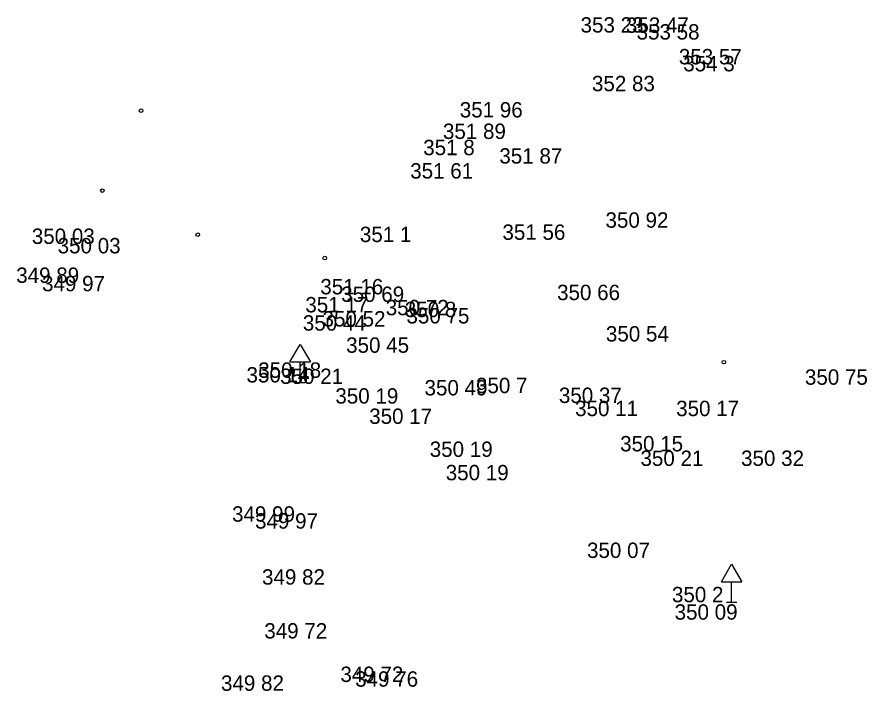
# Model space of a CAD drawing. Extents: x -688316 to -688024, y -973785 to -973591.
# Drawn here: x -688234.74 to -688193.31, y -973766.48 to -973733.6 of the extents above; entities that cross this region are included whole.
import ezdxf

# ---------------------------------------------------------------- set-up
doc = ezdxf.new("R2010")
doc.units = 0
for name, color, linetype in [('Vrstva 3', 7, 'Continuous'), ('Vrstva 34', 7, 'Continuous'), ('Vrstva 58', 7, 'Continuous')]:
    doc.layers.add(name, color=color, linetype=linetype)

# ---------------------------------------------------------------- blocks, each defined once
blk = doc.blocks.new('DZ')
at = {"layer": 'Vrstva 34'}
for p, q in [((-5, 10), (0, 18.5)), ((0, 18.5), (5, 10)), ((-5, 10), (5, 10)), ((0, 0), (0, 10)), ((-2.49, 0), (2.49, 0))]:
    blk.add_line(p, q, dxfattribs=at)
blk = doc.blocks.new('B_NESP')
at = {"layer": 'Vrstva 58'}
blk.add_circle((0, 0), 0.875, dxfattribs=at)

msp = doc.modelspace()

# ---------------------------------------------------------------- block references
at = {"layer": 'Vrstva 34', "xscale": 0.1, "yscale": 0.10000000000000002}
for p in [(-688220.94, -973751.43), (-688220.94, -973751.43), (-688199.91, -973762.15), (-688199.91, -973762.15)]:
    msp.add_blockref('DZ', p, dxfattribs=at)
at = {"layer": 'Vrstva 58', "xscale": 0.1, "yscale": 0.10000000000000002}
for p in [(-688228.69, -973738.17), (-688228.69, -973738.17), (-688230.58, -973742.07), (-688230.58, -973742.07), (-688225.93, -973744.22), (-688225.93, -973744.22), (-688219.74, -973745.36), (-688219.74, -973745.36), (-688200.29, -973750.44), (-688200.29, -973750.44)]:
    msp.add_blockref('B_NESP', p, dxfattribs=at)

# ---------------------------------------------------------------- texts
at = {"layer": 'Vrstva 3'}
for s, p in [('353 23 ', (-688207.271, -973734.36)), ('353 23 ', (-688207.271, -973734.36)), ('353 23 ', (-688207.271, -973734.36)), ('353 23 ', (-688207.271, -973734.36)), ('353 23 ', (-688207.271, -973734.36)), ('353 23 ', (-688207.271, -973734.36)), ('353 23 ', (-688207.271, -973734.36)), ('353 47 ', (-688205.061, -973734.37)), ('353 47 ', (-688205.061, -973734.37)), ('353 47 ', (-688205.061, -973734.37)), ('353 47 ', (-688205.061, -973734.37)), ('353 47 ', (-688205.061, -973734.37)), ('353 47 ', (-688205.061, -973734.37)), ('353 47 ', (-688205.061, -973734.37)), ('353 58 ', (-688204.541, -973734.7)), ('353 58 ', (-688204.541, -973734.7)), ('353 58 ', (-688204.541, -973734.7)), ('353 58 ', (-688204.541, -973734.7)), ('353 58 ', (-688204.541, -973734.7)), ('353 58 ', (-688204.541, -973734.7)), ('353 58 ', (-688204.541, -973734.7)), ('353 57 ', (-688202.481, -973735.91)), ('353 57 ', (-688202.481, -973735.91)), ('353 57 ', (-688202.481, -973735.91)), ('353 57 ', (-688202.481, -973735.91)), ('353 57 ', (-688202.481, -973735.91)), ('353 57 ', (-688202.481, -973735.91)), ('353 57 ', (-688202.481, -973735.91)), ('354 3  ', (-688202.268, -973736.25)), ('354 3  ', (-688202.268, -973736.25)), ('354 3  ', (-688202.268, -973736.25)), ('354 3  ', (-688202.268, -973736.25)), ('354 3  ', (-688202.268, -973736.25)), ('354 3  ', (-688202.268, -973736.25)), ('354 3  ', (-688202.268, -973736.25)), ('352 83 ', (-688206.717, -973737.22)), ('352 83 ', (-688206.717, -973737.22)), ('352 83 ', (-688206.717, -973737.22)), ('352 83 ', (-688206.717, -973737.22)), ('352 83 ', (-688206.717, -973737.22)), ('352 83 ', (-688206.717, -973737.22)), ('352 83 ', (-688206.717, -973737.22)), ('351 96 ', (-688213.159, -973738.5)), ('351 96 ', (-688213.159, -973738.5)), ('351 96 ', (-688213.159, -973738.5)), ('351 96 ', (-688213.159, -973738.5)), ('351 96 ', (-688213.159, -973738.5)), ('351 96 ', (-688213.159, -973738.5)), ('351 96 ', (-688213.159, -973738.5)), ('351 89 ', (-688213.979, -973739.55)), ('351 89 ', (-688213.979, -973739.55)), ('351 89 ', (-688213.979, -973739.55)), ('351 89 ', (-688213.979, -973739.55)), ('351 89 ', (-688213.979, -973739.55)), ('351 89 ', (-688213.979, -973739.55)), ('351 89 ', (-688213.979, -973739.55)), ('351 8  ', (-688214.941, -973740.34)), ('351 8  ', (-688214.941, -973740.34)), ('351 8  ', (-688214.941, -973740.34)), ('351 8  ', (-688214.941, -973740.34)), ('351 8  ', (-688214.941, -973740.34)), ('351 8  ', (-688214.941, -973740.34)), ('351 8  ', (-688214.941, -973740.34)), ('351 87 ', (-688211.229, -973740.75)), ('351 87 ', (-688211.229, -973740.75)), ('351 87 ', (-688211.229, -973740.75)), ('351 87 ', (-688211.229, -973740.75)), ('351 87 ', (-688211.229, -973740.75)), ('351 87 ', (-688211.229, -973740.75)), ('351 87 ', (-688211.229, -973740.75)), ('351 61 ', (-688215.574, -973741.48)), ('351 61 ', (-688215.574, -973741.48)), ('351 61 ', (-688215.574, -973741.48)), ('351 61 ', (-688215.574, -973741.48)), ('351 61 ', (-688215.574, -973741.48)), ('351 61 ', (-688215.574, -973741.48)), ('351 61 ', (-688215.574, -973741.48)), ('350 92 ', (-688206.057, -973743.88)), ('350 92 ', (-688206.057, -973743.88)), ('350 92 ', (-688206.057, -973743.88)), ('350 92 ', (-688206.057, -973743.88)), ('350 92 ', (-688206.057, -973743.88)), ('350 92 ', (-688206.057, -973743.88)), ('350 92 ', (-688206.057, -973743.88)), ('350 03 ', (-688234.017, -973744.67)), ('350 03 ', (-688234.017, -973744.67)), ('350 03 ', (-688234.017, -973744.67)), ('350 03 ', (-688234.017, -973744.67)), ('350 03 ', (-688234.017, -973744.67)), ('350 03 ', (-688234.017, -973744.67)), ('350 03 ', (-688234.017, -973744.67)), ('351 1  ', (-688218.026, -973744.58)), ('351 1  ', (-688218.026, -973744.58)), ('351 1  ', (-688218.026, -973744.58)), ('351 1  ', (-688218.026, -973744.58)), ('351 1  ', (-688218.026, -973744.58)), ('351 1  ', (-688218.026, -973744.58)), ('351 1  ', (-688218.026, -973744.58)), ('351 56 ', (-688211.079, -973744.47)), ('351 56 ', (-688211.079, -973744.47)), ('351 56 ', (-688211.079, -973744.47)), ('351 56 ', (-688211.079, -973744.47)), ('351 56 ', (-688211.079, -973744.47)), ('351 56 ', (-688211.079, -973744.47)), ('351 56 ', (-688211.079, -973744.47)), ('350 03 ', (-688232.757, -973745.13)), ('350 03 ', (-688232.757, -973745.13)), ('350 03 ', (-688232.757, -973745.13)), ('350 03 ', (-688232.757, -973745.13)), ('350 03 ', (-688232.757, -973745.13)), ('350 03 ', (-688232.757, -973745.13)), ('350 03 ', (-688232.757, -973745.13)), ('349 89 ', (-688234.777, -973746.57)), ('349 89 ', (-688234.777, -973746.57)), ('349 89 ', (-688234.777, -973746.57)), ('349 89 ', (-688234.777, -973746.57)), ('349 89 ', (-688234.777, -973746.57)), ('349 89 ', (-688234.777, -973746.57)), ('349 89 ', (-688234.777, -973746.57)), ('349 97 ', (-688233.517, -973746.98)), ('349 97 ', (-688233.517, -973746.98)), ('349 97 ', (-688233.517, -973746.98)), ('349 97 ', (-688233.517, -973746.98)), ('349 97 ', (-688233.517, -973746.98)), ('349 97 ', (-688233.517, -973746.98)), ('349 97 ', (-688233.517, -973746.98)), ('351 16 ', (-688219.955, -973747.13)), ('351 16 ', (-688219.955, -973747.13)), ('351 16 ', (-688219.955, -973747.13)), ('351 16 ', (-688219.955, -973747.13)), ('351 16 ', (-688219.955, -973747.13)), ('351 16 ', (-688219.955, -973747.13)), ('351 16 ', (-688219.955, -973747.13)), ('350 69 ', (-688218.936, -973747.5)), ('350 69 ', (-688218.936, -973747.5)), ('350 69 ', (-688218.936, -973747.5)), ('350 69 ', (-688218.936, -973747.5)), ('350 69 ', (-688218.936, -973747.5)), ('350 69 ', (-688218.936, -973747.5)), ('350 69 ', (-688218.936, -973747.5)), ('350 66 ', (-688208.416, -973747.41)), ('350 66 ', (-688208.416, -973747.41)), ('350 66 ', (-688208.416, -973747.41)), ('350 66 ', (-688208.416, -973747.41)), ('350 66 ', (-688208.416, -973747.41)), ('350 66 ', (-688208.416, -973747.41)), ('350 66 ', (-688208.416, -973747.41)), ('351 17 ', (-688220.685, -973748.01)), ('351 17 ', (-688220.685, -973748.01)), ('351 17 ', (-688220.685, -973748.01)), ('351 17 ', (-688220.685, -973748.01)), ('351 17 ', (-688220.685, -973748.01)), ('351 17 ', (-688220.685, -973748.01)), ('351 17 ', (-688220.685, -973748.01)), ('350 72 ', (-688216.767, -973748.15)), ('350 72 ', (-688216.767, -973748.15)), ('350 72 ', (-688216.767, -973748.15)), ('350 72 ', (-688216.767, -973748.15)), ('350 72 ', (-688216.767, -973748.15)), ('350 72 ', (-688216.767, -973748.15)), ('350 72 ', (-688216.767, -973748.15)), ('350 8  ', (-688215.838, -973748.24)), ('350 8  ', (-688215.838, -973748.24)), ('350 8  ', (-688215.838, -973748.24)), ('350 8  ', (-688215.838, -973748.24)), ('350 8  ', (-688215.838, -973748.24)), ('350 8  ', (-688215.838, -973748.24)), ('350 8  ', (-688215.838, -973748.24)), ('350 44 ', (-688220.807, -973748.9)), ('350 44 ', (-688220.807, -973748.9)), ('350 44 ', (-688220.807, -973748.9)), ('350 44 ', (-688220.807, -973748.9)), ('350 44 ', (-688220.807, -973748.9)), ('350 44 ', (-688220.807, -973748.9)), ('350 44 ', (-688220.807, -973748.9)), ('350 52 ', (-688219.847, -973748.7)), ('350 52 ', (-688219.847, -973748.7)), ('350 52 ', (-688219.847, -973748.7)), ('350 52 ', (-688219.847, -973748.7)), ('350 52 ', (-688219.847, -973748.7)), ('350 52 ', (-688219.847, -973748.7)), ('350 52 ', (-688219.847, -973748.7)), ('350 75 ', (-688215.757, -973748.55)), ('350 75 ', (-688215.757, -973748.55)), ('350 75 ', (-688215.757, -973748.55)), ('350 75 ', (-688215.757, -973748.55)), ('350 75 ', (-688215.757, -973748.55)), ('350 75 ', (-688215.757, -973748.55)), ('350 75 ', (-688215.757, -973748.55)), ('350 54 ', (-688206.037, -973749.43)), ('350 54 ', (-688206.037, -973749.43)), ('350 54 ', (-688206.037, -973749.43)), ('350 54 ', (-688206.037, -973749.43)), ('350 54 ', (-688206.037, -973749.43)), ('350 54 ', (-688206.037, -973749.43)), ('350 54 ', (-688206.037, -973749.43)), ('350 45 ', (-688218.697, -973749.98)), ('350 45 ', (-688218.697, -973749.98)), ('350 45 ', (-688218.697, -973749.98)), ('350 45 ', (-688218.697, -973749.98)), ('350 45 ', (-688218.697, -973749.98)), ('350 45 ', (-688218.697, -973749.98)), ('350 45 ', (-688218.697, -973749.98)), ('350 18 ', (-688222.983, -973751.2)), ('350 18 ', (-688222.983, -973751.2)), ('350 18 ', (-688222.983, -973751.2)), ('350 18 ', (-688222.983, -973751.2)), ('350 18 ', (-688222.983, -973751.2)), ('350 18 ', (-688222.983, -973751.2)), ('350 18 ', (-688222.983, -973751.2)), ('350 14 ', (-688223.553, -973751.43)), ('350 14 ', (-688223.553, -973751.43)), ('350 14 ', (-688223.553, -973751.43)), ('350 14 ', (-688223.553, -973751.43)), ('350 14 ', (-688223.553, -973751.43)), ('350 14 ', (-688223.553, -973751.43)), ('350 14 ', (-688223.553, -973751.43)), ('350 21 ', (-688221.913, -973751.5)), ('350 21 ', (-688221.913, -973751.5)), ('350 21 ', (-688221.913, -973751.5)), ('350 21 ', (-688221.913, -973751.5)), ('350 21 ', (-688221.913, -973751.5)), ('350 21 ', (-688221.913, -973751.5)), ('350 21 ', (-688221.913, -973751.5)), ('350 75 ', (-688196.337, -973751.54)), ('350 75 ', (-688196.337, -973751.54)), ('350 75 ', (-688196.337, -973751.54)), ('350 75 ', (-688196.337, -973751.54)), ('350 75 ', (-688196.337, -973751.54)), ('350 75 ', (-688196.337, -973751.54)), ('350 75 ', (-688196.337, -973751.54)), ('350 49 ', (-688214.877, -973752.06)), ('350 49 ', (-688214.877, -973752.06)), ('350 49 ', (-688214.877, -973752.06)), ('350 49 ', (-688214.877, -973752.06)), ('350 49 ', (-688214.877, -973752.06)), ('350 49 ', (-688214.877, -973752.06)), ('350 49 ', (-688214.877, -973752.06)), ('350 7  ', (-688212.368, -973751.95)), ('350 7  ', (-688212.368, -973751.95)), ('350 7  ', (-688212.368, -973751.95)), ('350 7  ', (-688212.368, -973751.95)), ('350 7  ', (-688212.368, -973751.95)), ('350 7  ', (-688212.368, -973751.95)), ('350 7  ', (-688212.368, -973751.95)), ('350 19 ', (-688219.223, -973752.46)), ('350 19 ', (-688219.223, -973752.46)), ('350 19 ', (-688219.223, -973752.46)), ('350 19 ', (-688219.223, -973752.46)), ('350 19 ', (-688219.223, -973752.46)), ('350 19 ', (-688219.223, -973752.46)), ('350 19 ', (-688219.223, -973752.46)), ('350 37 ', (-688208.329, -973752.43)), ('350 37 ', (-688208.329, -973752.43)), ('350 37 ', (-688208.329, -973752.43)), ('350 37 ', (-688208.329, -973752.43)), ('350 37 ', (-688208.329, -973752.43)), ('350 37 ', (-688208.329, -973752.43)), ('350 37 ', (-688208.329, -973752.43)), ('350 17 ', (-688217.573, -973753.45)), ('350 17 ', (-688217.573, -973753.45)), ('350 17 ', (-688217.573, -973753.45)), ('350 17 ', (-688217.573, -973753.45)), ('350 17 ', (-688217.573, -973753.45)), ('350 17 ', (-688217.573, -973753.45)), ('350 17 ', (-688217.573, -973753.45)), ('350 11 ', (-688207.538, -973753.07)), ('350 11 ', (-688207.538, -973753.07)), ('350 11 ', (-688207.538, -973753.07)), ('350 11 ', (-688207.538, -973753.07)), ('350 11 ', (-688207.538, -973753.07)), ('350 11 ', (-688207.538, -973753.07)), ('350 11 ', (-688207.538, -973753.07)), ('350 17 ', (-688202.613, -973753.07)), ('350 17 ', (-688202.613, -973753.07)), ('350 17 ', (-688202.613, -973753.07)), ('350 17 ', (-688202.613, -973753.07)), ('350 17 ', (-688202.613, -973753.07)), ('350 17 ', (-688202.613, -973753.07)), ('350 17 ', (-688202.613, -973753.07)), ('350 19 ', (-688214.623, -973755.06)), ('350 19 ', (-688214.623, -973755.06)), ('350 19 ', (-688214.623, -973755.06)), ('350 19 ', (-688214.623, -973755.06)), ('350 19 ', (-688214.623, -973755.06)), ('350 19 ', (-688214.623, -973755.06)), ('350 19 ', (-688214.623, -973755.06)), ('350 15 ', (-688205.343, -973754.79)), ('350 15 ', (-688205.343, -973754.79)), ('350 15 ', (-688205.343, -973754.79)), ('350 15 ', (-688205.343, -973754.79)), ('350 15 ', (-688205.343, -973754.79)), ('350 15 ', (-688205.343, -973754.79)), ('350 15 ', (-688205.343, -973754.79)), ('350 21 ', (-688204.353, -973755.5)), ('350 21 ', (-688204.353, -973755.5)), ('350 21 ', (-688204.353, -973755.5)), ('350 21 ', (-688204.353, -973755.5)), ('350 21 ', (-688204.353, -973755.5)), ('350 21 ', (-688204.353, -973755.5)), ('350 21 ', (-688204.353, -973755.5)), ('350 32 ', (-688199.449, -973755.5)), ('350 32 ', (-688199.449, -973755.5)), ('350 32 ', (-688199.449, -973755.5)), ('350 32 ', (-688199.449, -973755.5)), ('350 32 ', (-688199.449, -973755.5)), ('350 32 ', (-688199.449, -973755.5)), ('350 32 ', (-688199.449, -973755.5)), ('350 19 ', (-688213.843, -973756.2)), ('350 19 ', (-688213.843, -973756.2)), ('350 19 ', (-688213.843, -973756.2)), ('350 19 ', (-688213.843, -973756.2)), ('350 19 ', (-688213.843, -973756.2)), ('350 19 ', (-688213.843, -973756.2)), ('350 19 ', (-688213.843, -973756.2)), ('349 99 ', (-688224.257, -973758.22)), ('349 99 ', (-688224.257, -973758.22)), ('349 99 ', (-688224.257, -973758.22)), ('349 99 ', (-688224.257, -973758.22)), ('349 99 ', (-688224.257, -973758.22)), ('349 99 ', (-688224.257, -973758.22)), ('349 99 ', (-688224.257, -973758.22)), ('349 97 ', (-688223.137, -973758.56)), ('349 97 ', (-688223.137, -973758.56)), ('349 97 ', (-688223.137, -973758.56)), ('349 97 ', (-688223.137, -973758.56)), ('349 97 ', (-688223.137, -973758.56)), ('349 97 ', (-688223.137, -973758.56)), ('349 97 ', (-688223.137, -973758.56)), ('350 07 ', (-688206.957, -973759.99)), ('350 07 ', (-688206.957, -973759.99)), ('350 07 ', (-688206.957, -973759.99)), ('350 07 ', (-688206.957, -973759.99)), ('350 07 ', (-688206.957, -973759.99)), ('350 07 ', (-688206.957, -973759.99)), ('350 07 ', (-688206.957, -973759.99)), ('349 82 ', (-688222.797, -973761.29)), ('349 82 ', (-688222.797, -973761.29)), ('349 82 ', (-688222.797, -973761.29)), ('349 82 ', (-688222.797, -973761.29)), ('349 82 ', (-688222.797, -973761.29)), ('349 82 ', (-688222.797, -973761.29)), ('349 82 ', (-688222.797, -973761.29)), ('350 2  ', (-688202.818, -973762.15)), ('350 2  ', (-688202.818, -973762.15)), ('350 2  ', (-688202.818, -973762.15)), ('350 2  ', (-688202.818, -973762.15)), ('350 2  ', (-688202.818, -973762.15)), ('350 2  ', (-688202.818, -973762.15)), ('350 2  ', (-688202.818, -973762.15)), ('350 09 ', (-688202.687, -973763)), ('350 09 ', (-688202.687, -973763)), ('350 09 ', (-688202.687, -973763)), ('350 09 ', (-688202.687, -973763)), ('350 09 ', (-688202.687, -973763)), ('350 09 ', (-688202.687, -973763)), ('350 09 ', (-688202.687, -973763)), ('349 72 ', (-688222.687, -973763.92)), ('349 72 ', (-688222.687, -973763.92)), ('349 72 ', (-688222.687, -973763.92)), ('349 72 ', (-688222.687, -973763.92)), ('349 72 ', (-688222.687, -973763.92)), ('349 72 ', (-688222.687, -973763.92)), ('349 72 ', (-688222.687, -973763.92)), ('349 72 ', (-688218.977, -973766.04)), ('349 72 ', (-688218.977, -973766.04)), ('349 72 ', (-688218.977, -973766.04)), ('349 72 ', (-688218.977, -973766.04)), ('349 72 ', (-688218.977, -973766.04)), ('349 72 ', (-688218.977, -973766.04)), ('349 72 ', (-688218.977, -973766.04)), ('349 76 ', (-688218.257, -973766.27)), ('349 76 ', (-688218.257, -973766.27)), ('349 76 ', (-688218.257, -973766.27)), ('349 76 ', (-688218.257, -973766.27)), ('349 76 ', (-688218.257, -973766.27)), ('349 76 ', (-688218.257, -973766.27)), ('349 76 ', (-688218.257, -973766.27)), ('349 82 ', (-688224.797, -973766.47)), ('349 82 ', (-688224.797, -973766.47)), ('349 82 ', (-688224.797, -973766.47)), ('349 82 ', (-688224.797, -973766.47)), ('349 82 ', (-688224.797, -973766.47)), ('349 82 ', (-688224.797, -973766.47)), ('349 82 ', (-688224.797, -973766.47))]:
    msp.add_text(s, height=0.75, dxfattribs=at).set_placement(p)

doc.saveas('drawing.dxf')
